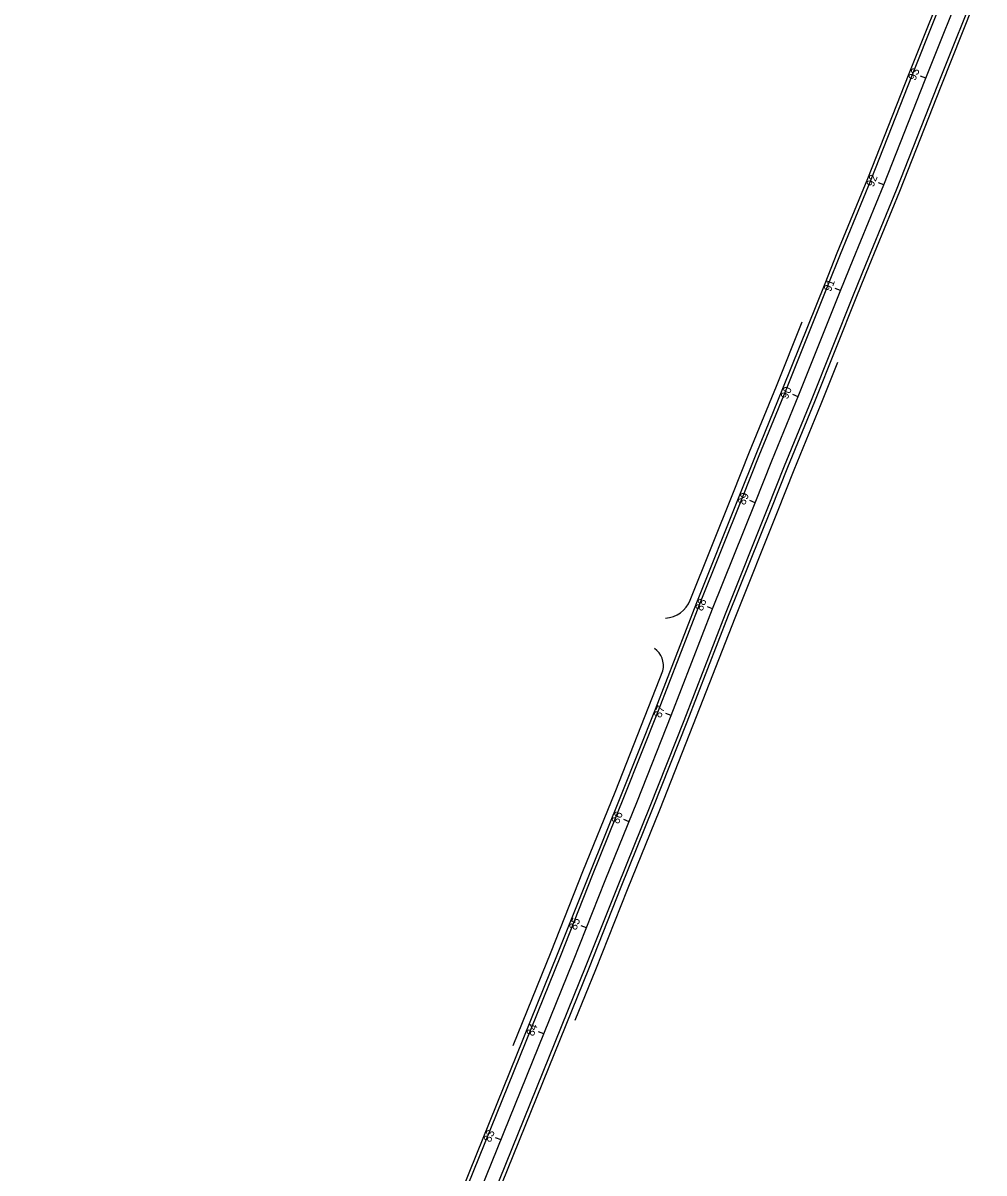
# Model space of a CAD drawing. Extents: x 2318076 to 2324211, y 613525 to 629939.
# Drawn here: x 2318974 to 2319815, y 623020 to 624026 of the extents above; entities that cross this region are included whole.
import ezdxf

# ---------------------------------------------------------------- set-up
doc = ezdxf.new("R2010")
doc.units = 0
for name, color, linetype in [('GE_P_CL_50', 7, 'Continuous'), ('PV_P_EOP', 7, 'Continuous'), ('PV_P_Shoulder', 7, 'Continuous'), ('RD_X_GR_Lt', 7, 'Continuous'), ('RD_X_GR_Rt', 7, 'Continuous')]:
    doc.layers.add(name, color=color, linetype=linetype)

msp = doc.modelspace()

# ---------------------------------------------------------------- linework, layer by layer
at = {"layer": 'GE_P_CL_50'}
for p, q in [((2319763.5, 623977.5), (2319758.9, 623979.4)), ((2319726.9, 623884.4), (2319722.3, 623886.2)), ((2319689.1, 623791.8), (2319684.4, 623793.7)), ((2319651.9, 623699), (2319647.3, 623700.9)), ((2319614.3, 623606.3), (2319609.7, 623608.2)), ((2319577.1, 623513.5), (2319572.5, 623515.4)), ((2319540.9, 623420.3), (2319536.3, 623422.1)), ((2319504, 623327.4), (2319499.3, 623329.2)), ((2319466.8, 623234.5), (2319462.1, 623236.4)), ((2319429.5, 623141.8), (2319424.8, 623143.6)), ((2319392, 623049.1), (2319387.3, 623050.9))]:
    msp.add_line(p, q, dxfattribs=at)
msp.add_lwpolyline([(2318973.8, 622036.6), (2319010.1, 622124.9), (2319049.4, 622216.8), (2319089, 622312.5), (2319126.1, 622401.5), (2319164.4, 622493.9), (2319203.1, 622586.1), (2319241.6, 622679), (2319271.8, 622752.1), (2319455.4, 623205.9), (2319483.2, 623276), (2319511.3, 623345.5), (2319540.9, 623420.3), (2319577.1, 623513.5), (2319614.3, 623606.3), (2319629, 623643.1), (2319652.5, 623700.6), (2319689.4, 623792.6), (2319700.1, 623819.1), (2319726.9, 623884.4), (2319763, 623976.2), (2319763, 623976.2), (2319800.6, 624070.3)], dxfattribs=at)
at = {"layer": 'PV_P_EOP'}
for points in [[(2318985, 622095.4), (2318999, 622129.5), (2319038.3, 622221.5), (2319077.9, 622317.1), (2319115, 622406.2), (2319153.3, 622498.5), (2319192, 622590.8), (2319230.5, 622683.5), (2319260.7, 622756.6), (2319444.3, 623210.4), (2319472.1, 623280.5), (2319500.1, 623349.9), (2319529.8, 623424.7), (2319566, 623517.9), (2319603.2, 623610.8), (2319617.9, 623647.6), (2319641.4, 623705.1), (2319678.2, 623797), (2319689, 623823.7), (2319715.8, 623888.9), (2319751.9, 623980.7), (2319789.4, 624074.7)], [(2319007.2, 622086.4), (2319021.1, 622120.3), (2319060.4, 622212.2), (2319100.1, 622307.9), (2319137.2, 622396.9), (2319175.5, 622489.3), (2319214.2, 622581.5), (2319252.7, 622674.4), (2319282.9, 622747.5), (2319466.6, 623201.5), (2319494.4, 623271.6), (2319522.4, 623341), (2319552.1, 623415.9), (2319588.3, 623509.1), (2319625.5, 623601.9), (2319640.1, 623638.6), (2319663.6, 623696.1), (2319700.5, 623788.1), (2319711.2, 623814.6), (2319738, 623879.9), (2319774.2, 623971.8), (2319811.7, 624065.9)]]:
    msp.add_lwpolyline(points, dxfattribs=at)
at = {"layer": 'PV_P_Shoulder'}
for points in [[(2318982.2, 622096.6), (2318996.2, 622130.7), (2319035.6, 622222.7), (2319075.2, 622318.2), (2319112.2, 622407.3), (2319150.5, 622499.7), (2319189.2, 622591.9), (2319227.7, 622684.7), (2319257.9, 622757.8), (2319441.5, 623211.5), (2319469.3, 623281.6), (2319497.3, 623351.1), (2319527, 623425.8), (2319563.2, 623519), (2319600.4, 623611.9), (2319615.1, 623648.7), (2319638.6, 623706.2), (2319675.5, 623798.2), (2319686.2, 623824.8), (2319713, 623890), (2319749.1, 623981.8), (2319786.6, 624075.9)], [(2319010, 622085.2), (2319023.9, 622119.1), (2319063.2, 622211), (2319102.9, 622306.7), (2319139.9, 622395.8), (2319178.2, 622488.1), (2319216.9, 622580.4), (2319255.5, 622673.2), (2319285.7, 622746.4), (2319469.4, 623200.3), (2319497.2, 623270.4), (2319525.2, 623339.9), (2319554.9, 623414.8), (2319591.1, 623508), (2319628.3, 623600.8), (2319642.9, 623637.4), (2319666.4, 623694.9), (2319703.3, 623787), (2319714, 623813.5), (2319740.8, 623878.8), (2319777, 623970.7), (2319814.5, 624064.8)]]:
    msp.add_lwpolyline(points, dxfattribs=at)
at = {"layer": 'RD_X_GR_Lt'}
for points in [[(2319557.5, 623521), (2319557.6, 623521.2), (2319594.8, 623614.1), (2319609.5, 623650.9), (2319633.1, 623708.4), (2319655.5, 623764.5)], [(2319402.7, 623131.7), (2319435.9, 623213.7), (2319463.7, 623283.8), (2319491.8, 623353.3), (2319521.4, 623428), (2319533.6, 623459.4)]]:
    msp.add_lwpolyline(points, dxfattribs=at)
for centre, radius, start, end in [((2319534.4, 623530.1), 24.8, 273.5693, 339.0635), ((2319515.2, 623463.6), 18.9, 347.1986, 54.2037)]:
    msp.add_arc(centre, radius, start, end, dxfattribs=at)
at = {"layer": 'RD_X_GR_Rt'}
msp.add_lwpolyline([(2319457, 623153.7), (2319474.9, 623198.1), (2319502.7, 623268.2), (2319530.8, 623337.7), (2319560.5, 623412.6), (2319596.7, 623505.8), (2319633.8, 623598.5), (2319648.5, 623635.2), (2319672, 623692.7), (2319686.7, 623729.4)], dxfattribs=at)

# ---------------------------------------------------------------- texts
at = {"layer": 'GE_P_CL_50'}
for s, rotation, p in [('93', 67.3411, (2319754.4, 623975)), ('92', 68.3373, (2319717.8, 623881.9)), ('91', 68.0408, (2319680.4, 623790.4)), ('90', 67.7618, (2319642.7, 623696.4)), ('89', 68.2266, (2319605.3, 623603.8)), ('88', 68.1454, (2319568.1, 623511.1)), ('87', 68.3591, (2319531.8, 623417.6)), ('86', 68.0338, (2319494.9, 623324.9)), ('85', 68.358, (2319457.7, 623232)), ('84', 68.5128, (2319420.4, 623139.3)), ('83', 68.3971, (2319382.9, 623046.5))]:
    msp.add_text(s, height=7, rotation=rotation, dxfattribs=at).set_placement(p)

doc.saveas('drawing.dxf')
